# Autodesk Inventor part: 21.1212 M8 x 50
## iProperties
Created: 2006-02
Part Number: 21.1212 M8 x 50
Material: Steel, Mild
Description: Cylinder Head Cap Screw
Document SubType Name: Modeling
Standard: DIN 7984
Designer: Andy Moles
Standards Organization: DIN
Language: en-US
Size Designation: M8 x 50
Categories: <MemberInstance><Categories><Category DisplayName="Fasteners" InternalName="e4da775c-781d-43d5-af7c-5136215cf5a6" Mnemonic="FSTN"><Category DisplayName="Bolts"
Density: 7.86 g/cm^3
Mass: 24.1156 g
Surface Area: 17.7165 cm^2
Volume: 3.06815 cm^3
Author: Andy Moles
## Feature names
1. Body [Revolution]
2. Slot [Extrusion]
3. Fillet1
4. Chamfer1
